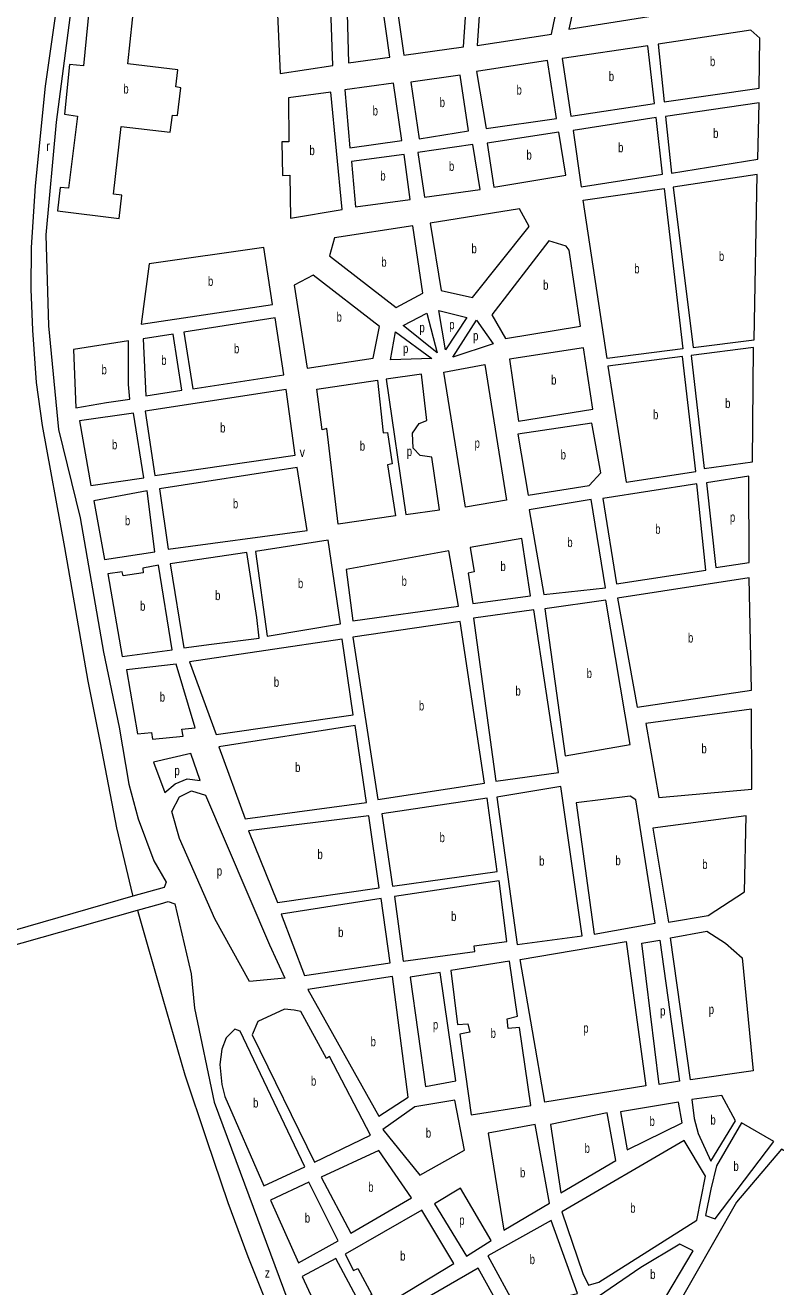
# Model space of a CAD drawing. Extents: x 639657 to 671642, y 222838 to 252123.
# Drawn here: x 649779 to 650568, y 239098 to 240424 of the extents above; entities that cross this region are included whole.
import ezdxf

# ---------------------------------------------------------------- set-up
doc = ezdxf.new("R2010")
doc.units = 0
doc.header["$LTSCALE"] = 4
doc.layers.add('1', color=7, linetype='Continuous', lineweight=13)
doc.layers.add('5', color=7, linetype='Continuous', lineweight=13)
doc.layers.add('7', color=7, linetype='Continuous')

msp = doc.modelspace()

# ---------------------------------------------------------------- linework, layer by layer
at = {"layer": '1'}
msp.add_line((649892.647, 239508.316), (649663.962, 239442.471), dxfattribs=at)
for points in [[(649918.026, 241075.888), (649933.25, 241068.002), (649916.64, 241006.75), (649899.23, 240914.55), (649833.69, 240489.25), (649812, 240322.2), (649801.13, 240203.85), (649803.92, 240108.11), (649814.45, 239999.23), (649837.26, 239906.37), (649861.82, 239765.17), (649878.15, 239686.26), (649888.52, 239626.13), (649898.01, 239589.86), (649914.52, 239545.63), (649927.53, 239523.01), (649925.34, 239517.73), (649892.647, 239508.316)], [(649665.539, 239427.483), (649715.29, 239442.31), (649897.418, 239493.698)], [(649897.418, 239493.698), (649921.63, 239500.53), (649929.68, 239502.7), (649936.8, 239500.43), (649953.91, 239426.9), (649957.52, 239390.57), (649978.06, 239291.74), (650064.64, 239058.86), (650104.11, 238963.89), (650145.17, 238876.98), (650175.39, 238826.04), (650230.01, 238717.98), (650262.92, 238636.13), (650251.614, 238630.278)]]:
    msp.add_lwpolyline(points, dxfattribs=at)
for points in [[(650457.47, 240552.72), (650383.62, 240568.34), (650350.89, 240420.19), (650434.89, 240433.55)], [(650041.99, 240498.37), (650047.42, 240373.59), (650102.77, 240381.72), (650098.7, 240501.47)], [(650147.02, 240502.88), (650116.23, 240501.55), (650119.29, 240384.57), (650162.9, 240390.5)], [(650246.22, 240490.22), (650166.36, 240507.56), (650161.84, 240503.71), (650177.3, 240392.83), (650240.03, 240401.51)], [(650343.68, 240467.24), (650260.17, 240485.89), (650254.42, 240402.98), (650332.84, 240414.85)], [(649816.2, 240253.51), (649813.42, 240229.05), (649878.2, 240221.16), (649881.04, 240245.43), (649872.24, 240246.74), (649880.33, 240317.83), (649931.86, 240311.71), (649934.22, 240329.73), (649939.62, 240329.2), (649942.91, 240358.51), (649937.66, 240359.3), (649939.73, 240377.42), (649887.33, 240383.55), (649894.79, 240453.34), (649905.52, 240451.82), (649907.93, 240476.95), (649842.01, 240483.53), (649838.3, 240458.4), (649847.97, 240457.09), (649840.73, 240381.47), (649826.12, 240382.81), (649820.62, 240330.7), (649834.55, 240328.66), (649824.78, 240252.85)], [(650444.71, 240404.31), (650451.03, 240343.51), (650551.14, 240358.12), (650551.89, 240410.54), (650542.46, 240418.93)], [(650441.15, 240341.81), (650433.97, 240402.4), (650343.95, 240389.27), (650353.06, 240328.46)], [(650337.81, 240326.12), (650328.48, 240386.94), (650253.93, 240375.49), (650263.91, 240315.53)], [(650245.43, 240313.21), (650236.53, 240371.56), (650184.94, 240364.37), (650193.44, 240304.72)], [(650112.53, 240230.56), (650100.76, 240353.89), (650056.07, 240347.97), (650056.62, 240301.57), (650049.11, 240301.58), (650049.89, 240266.35), (650057.59, 240266.53), (650058.18, 240221.44)], [(650175.39, 240302.83), (650166.71, 240363.21), (650115.58, 240356.22), (650120.61, 240295.42)], [(650549.7, 240283.37), (650551.11, 240342.44), (650452.72, 240328.25), (650458.82, 240268.73)], [(650442.62, 240327.2), (650355.39, 240313.63), (650364.08, 240254.11), (650449.37, 240267.46)], [(650340.57, 240311.73), (650264.95, 240300.28), (650272.16, 240253.87), (650347.78, 240266.6)], [(650177.73, 240288.43), (650122.3, 240281.02), (650126.5, 240233.33), (650184.07, 240240.94)], [(650250.13, 240298.81), (650192.34, 240290.33), (650199.33, 240243.27), (650257.76, 240251.53)], [(650481.77, 240085.44), (650545.66, 240093.27), (650548.81, 240267.26), (650460.51, 240253.91)], [(650470.9, 240083.97), (650391.32, 240073.89), (650365.98, 240240.14), (650451.27, 240252.64)], [(650249.58, 240137.91), (650309.23, 240212.55), (650298.96, 240231.04), (650205.28, 240215.98), (650216.74, 240145.28)], [(650169.45, 240127.34), (650197.62, 240142.53), (650186.81, 240213.23), (650104.53, 240200.72), (650099.33, 240181.83)], [(650330.03, 240197.47), (650269.95, 240119.83), (650284.5, 240094.66), (650363.35, 240107.61), (650351.27, 240187.75), (650348.27, 240192.06)], [(650039.52, 240130.39), (650030.41, 240190.35), (649909.67, 240173.41), (649901.17, 240109.84)], [(650145.07, 240074.11), (650151.8, 240107.39), (650082.11, 240161.46), (650062.33, 240150.76), (650075.9, 240063.51)], [(650051.4, 240056.69), (650042.28, 240116.43), (649946.25, 240101.37), (649955.8, 240042.06)], [(650176.6, 240108.55), (650201.536, 240121.458), (650212.503, 240079.908)], [(650214.384, 240124.333), (650243.839, 240116.754), (650221.121, 240083.044)], [(650253.893, 240114.141), (650271.258, 240089.316), (650228.955, 240075.204)], [(650163.595, 240072.448), (650168.633, 240101.859), (650207.019, 240073.636)], [(649864.7, 240027.64), (649889.41, 240031.03), (649888.15, 240046.28), (649888.03, 240092.25), (649830.02, 240083.14), (649832.69, 240021.91)], [(649906.17, 240034.65), (649944.19, 240040.58), (649935.08, 240099.46), (649903.5, 240094.58)], [(650376.06, 240020.58), (650366.53, 240084.83), (650288.54, 240072.96), (650298.07, 240007.85)], [(650411.35, 239943.9), (650484.32, 239954.99), (650470.46, 240075.81), (650392.04, 240065.66)], [(650493.12, 239958.04), (650543.97, 239965.17), (650545.22, 240085.32), (650479.69, 240077.08)], [(650262.603, 240067.603), (650285.359, 239924.685), (650242.272, 239917.63), (650219.554, 240059.525)], [(650096.43, 240000.12), (650091.68, 239998.95), (650086.16, 240041.58), (650149.75, 240050.9), (650155.76, 239995.52), (650160.38, 239995.86), (650165.3, 239963.11), (650160.47, 239962.03), (650168.633, 239908.222), (650108.311, 239899.599)], [(650159.05, 240052.16), (650179.6, 239909.79), (650214.853, 239914.494), (650207.019, 239970.155), (650194.485, 239971.723), (650187.434, 239979.562), (650186.651, 239995.241), (650193.702, 240005.433), (650201.536, 240008.568), (650196.052, 240057.173)], [(650063.22, 239971.97), (650053.69, 240041.35), (649905.49, 240018.29), (649915.57, 239950.63)], [(649904.29, 239948.45), (649893.38, 240016.34), (649836.5, 240008.3), (649848.45, 239940.24)], [(650384.48, 239953.5), (650375.22, 240005.72), (650297.42, 239994.29), (650308.078, 239930.173), (650372.4, 239940.14)], [(650065.4, 239959.08), (649920.44, 239936.67), (649929.74, 239873.32), (650075.79, 239893.05)], [(650485.49, 239941.95), (650386.7, 239926.65), (650400.91, 239836.98), (650494.87, 239851.2)], [(650540.26, 239950.15), (650495.69, 239943.05), (650505.61, 239853.92), (650540.5, 239859.38)], [(649907.55, 239934.49), (649851.72, 239924.13), (649862.63, 239862.39), (649915.78, 239870.59)], [(650324.67, 239825.5), (650389.64, 239832.65), (650374.35, 239925.54), (650309.38, 239914.62)], [(650097.84, 239882.9), (650021.6, 239870.88), (650033.66, 239781.75), (650110.97, 239794.85)], [(650301.41, 239884.52), (650247.16, 239875.19), (650251.55, 239849.47), (650244.95, 239847.94), (650250.03, 239816.17), (650310.71, 239824.39)], [(650012.47, 239869.78), (649931.93, 239857.75), (649946.14, 239769.69), (649975.13, 239773.53), (650025.271, 239779.656), (650022.86, 239801.59)], [(650224.64, 239871.42), (650116.72, 239851.8), (650123.85, 239798.1), (650235, 239813.44)], [(649881.46, 239849.55), (649866.43, 239847.36), (649881.17, 239760.39), (649933.79, 239767.51), (649919.58, 239856.64), (649902.94, 239853.37), (649903.49, 239848.54), (649882.55, 239845.26)], [(650540.55, 239843.27), (650402.03, 239821.95), (650422.69, 239707.02), (650543.02, 239725.1)], [(650313.97, 239809.36), (650250.61, 239800.59), (650274.18, 239629.31), (650340.22, 239638.62)], [(650389.68, 239819.76), (650325.78, 239810.46), (650347.15, 239655.83), (650415.34, 239667.83)], [(650236.65, 239797.33), (650123.9, 239780.91), (650150.15, 239610.18), (650262.37, 239627.13)], [(650112.63, 239778.74), (649952.09, 239754.67), (649980.23, 239678.47), (650124.12, 239699.27)], [(649938.13, 239752.48), (649886.04, 239746.44), (649897.41, 239679.09), (649912.01, 239680.44), (649913.1, 239673.46), (649945.32, 239676.77), (649943.94, 239684.02), (649958.19, 239685.4)], [(650431.93, 239689.89), (650445.57, 239612.05), (650543.3, 239620.9), (650543.07, 239705.23)], [(650126.3, 239688), (649982.95, 239665.59), (650010.55, 239589.93), (650138.34, 239606.92)], [(649914.259, 239649.308), (649926.111, 239617.378), (649937.029, 239626.482), (649949.766, 239631.945), (649963.414, 239630.124), (649953.406, 239658.349)], [(650342.41, 239623.59), (650275.3, 239612.66), (650296.67, 239457.49), (650364.86, 239466.8)], [(650052.299, 239422.071), (650015.274, 239418.895), (649978.881, 239484.449), (649941.578, 239569.123), (649933.39, 239597.347), (649941.578, 239612.825), (649954.315, 239619.198), (649968.873, 239614.646), (650036.2, 239457.135)], [(650265.09, 239611.56), (650154.49, 239595.15), (650165.44, 239518.91), (650275.51, 239534.24)], [(650415.49, 239613.58), (650358.57, 239606.44), (650377.75, 239468.45), (650441.63, 239479.9), (650421.4, 239609.83)], [(650140.53, 239592.96), (650014.2, 239577.04), (650044.63, 239501.93), (650151.48, 239517.26)], [(650537.47, 239592.96), (650439.21, 239579.8), (650455.6, 239481.01), (650497.47, 239488.11), (650535.54, 239512.92)], [(650277.68, 239524.58), (650167.62, 239508.17), (650176.93, 239439.98), (650252.19, 239450.25), (650251.55, 239456.29), (650285.92, 239460.68)], [(650153.66, 239505.98), (650048.42, 239489.59), (650072.97, 239424.95), (650162.97, 239438.33)], [(650457.696, 239464.681), (650496.173, 239471.753), (650515.804, 239459.181), (650533.08, 239443.464), (650544.859, 239324.807), (650478.898, 239315.378)], [(650299.86, 239441.893), (650411.366, 239460.752), (650431.782, 239309.091), (650325.773, 239291.803)], [(650445.739, 239310.383), (650427.856, 239459.181), (650446.702, 239462.324), (650467.119, 239313.806)], [(650288.66, 239440.28), (650226.91, 239430.45), (650234.05, 239373.53), (650244.79, 239374.1), (650246.97, 239365.51), (650236.23, 239363.33), (650248.28, 239278.5), (650311.1, 239288.33), (650299.05, 239370.48), (650287.24, 239369.38), (650286.14, 239379.58), (650296.87, 239382.29)], [(650215.64, 239428.27), (650183.96, 239423.35), (650200.39, 239308.45), (650232.07, 239314.44)], [(650165.45, 239424.04), (650076.58, 239410.26), (650151.06, 239277.16), (650182.16, 239297.12)], [(650024.02, 239376.73), (650018.15, 239362.74), (650083.51, 239228.64), (650142.52, 239257.26), (650099.32, 239339.87), (650096.11, 239337.71), (650069.11, 239387.05), (650062.13, 239388.64), (650051.92, 239389.69)], [(649989.32, 239297.67), (650030.4, 239203.79), (650073.32, 239223.78), (650005.25, 239366.47), (649999.87, 239368.6), (649990.77, 239359.45), (649985.97, 239347.62), (649983.86, 239331.5), (649986.07, 239310.56)], [(650189.17, 239286.93), (650155.39, 239263.21), (650194.2, 239214.97), (650241.39, 239241.42), (650231.05, 239294.03)], [(650466.32, 239291.97), (650405.11, 239281.6), (650412.2, 239241.87), (650470.14, 239269.96)], [(650480.427, 239294.507), (650482.824, 239274.518), (650486.75, 239258.801), (650500.099, 239229.726), (650526.013, 239272.16), (650511.878, 239298.878)], [(650391.15, 239280.49), (650331.56, 239268.51), (650342.5, 239196.57), (650400.42, 239230.56)], [(650315.45, 239268.47), (650266.05, 239259.21), (650282.45, 239157.2), (650330.71, 239185.8)], [(650566.34, 239250.35), (650532.45, 239270.13), (650506.25, 239224.94), (650500.18, 239200.48), (650494.67, 239172.84), (650504.79, 239169.07)], [(650472.34, 239251.7), (650343.63, 239176.7), (650365.64, 239111.8), (650371.77, 239099.43), (650382.5, 239102.68), (650485.46, 239167.95), (650494.46, 239214.16)], [(650151.16, 239241.17), (650090.54, 239213.08), (650121.85, 239154.08), (650185.67, 239191.31)], [(650729.9, 239152.49), (650574.42, 239242.31), (650527.3, 239186.86), (650458.88, 239066.9), (650621.89, 238971.19)], [(650077.66, 239207.67), (650037.43, 239188.77), (650066.61, 239122.78), (650108.45, 239145.99)], [(650209.556, 239184.935), (650243.321, 239129.929), (650269.235, 239146.431), (650237.039, 239201.437)], [(650143.93, 239089.51), (650139.76, 239086.99), (650147.46, 239072.03), (650229.9, 239122.14), (650196.45, 239178.45), (650115.65, 239131.99), (650124.64, 239114.88), (650129, 239116.94)], [(650332.37, 239167.54), (650265.87, 239130.3), (650295.56, 239075.59), (650359.98, 239090.8)], [(650405.77, 239069.07), (650446.15, 239075.89), (650481.78, 239135.71), (650467.8, 239142.65), (650426.75, 239117.9), (650382.01, 239087.64)], [(650070.566, 239108.712), (650099.62, 239045.847), (650138.098, 239067.064), (650105.902, 239127.571)], [(650255.7, 239117.38), (650161.85, 239062.88), (650182.91, 239021.04), (650278.91, 239075.54)]]:
    msp.add_lwpolyline(points, close=True, dxfattribs=at)
at = {"layer": '5'}
for p, q in [((649831.46, 240578.71), (649800.52, 240360.09)), ((649800.52, 240360.09), (649790, 240255.28)), ((649790, 240255.28), (649785.57, 240190.42)), ((649785.57, 240190.42), (649785.48, 240146.81)), ((649785.48, 240146.81), (649786.9, 240103.63)), ((649786.9, 240103.63), (649790.86, 240048.42)), ((649790.86, 240048.42), (649797.35, 240003.5)), ((649797.35, 240003.5), (649820.7, 239875.17)), ((649820.7, 239875.17), (649845.25, 239734.51)), ((649845.25, 239734.51), (649858.32, 239669.55)), ((649858.32, 239669.55), (649875.22, 239580.44)), ((649924.05, 239400.63), (649947.37, 239320.66)), ((649947.37, 239320.66), (649970.11, 239252.5)), ((649970.11, 239252.5), (649992.31, 239186.5)), ((649992.31, 239186.5), (650013.42, 239129.62)), ((650013.42, 239129.62), (650042.62, 239056.65))]:
    msp.add_line(p, q, dxfattribs=at)
for points in [[(649875.22, 239580.44), (649892.358, 239509.51), (649892.647, 239508.316)], [(649897.418, 239493.698), (649897.766, 239492.48), (649924.05, 239400.63)]]:
    msp.add_lwpolyline(points, dxfattribs=at)

# ---------------------------------------------------------------- texts
at = {"layer": '7'}
for s, width, p in [('b', 0.75, (650499.29, 240381.22)), ('b', 0.75, (650392.936, 240365.43)), ('b', 0.75, (649882.561, 240352.345)), ('b', 0.75, (650295.962, 240351.235)), ('b', 0.75, (650144.694, 240329.315)), ('b', 0.75, (650215.153, 240338.14)), ('b', 0.75, (650502.637, 240305.585)), ('r', 0.85, (649801.466, 240292.102)), ('b', 0.75, (650402.747, 240290.655)), ('b', 0.75, (650078.249, 240287.665)), ('b', 0.75, (650306.429, 240282.8)), ('b', 0.75, (650224.908, 240271.04)), ('b', 0.75, (650152.741, 240260.88)), ('b', 0.75, (650248.59, 240184.475)), ('b', 0.75, (650153.781, 240170.285)), ('b', 0.75, (650508.731, 240176.35)), ('b', 0.75, (650419.684, 240163.265)), ('b', 0.75, (649971.539, 240150.095)), ('b', 0.75, (650323.902, 240146.065)), ('b', 0.75, (650106.758, 240112.485)), ('p', 0.75, (650193.858, 240101.381)), ('p', 0.75, (650225.194, 240104.516)), ('p', 0.75, (650250.263, 240092.757)), ('b', 0.75, (649998.885, 240079.245)), ('b', 0.75, (649922.41, 240067.055)), ('p', 0.75, (650176.624, 240079.43)), ('b', 0.75, (649859.639, 240057.08)), ('b', 0.75, (650332.338, 240046.34)), ('b', 0.75, (650515.249, 240021.68)), ('b', 0.75, (650439.458, 240009.855)), ('b', 0.75, (649984.366, 239995.99)), ('b', 0.75, (649870.632, 239978.29)), ('b', 0.75, (650131.15, 239976.85)), ('p', 0.75, (650251.83, 239979.868)), ('v', 0.85, (650067.886, 239970.37)), ('p', 0.75, (650180.541, 239971.245)), ('b', 0.75, (650342.367, 239967.69)), ('b', 0.75, (649997.796, 239916.2)), ('b', 0.75, (649884.226, 239898.44)), ('p', 0.75, (650520.321, 239902.035)), ('b', 0.75, (650441.754, 239889.465)), ('b', 0.75, (650349.336, 239875.52)), ('b', 0.75, (650279.048, 239850.345)), ('b', 0.75, (650066.099, 239832.325)), ('b', 0.75, (650175.086, 239834.76)), ('b', 0.75, (649979.08, 239819.735)), ('b', 0.75, (649900.133, 239808.515)), ('b', 0.75, (650476.209, 239775.145)), ('b', 0.75, (650369.673, 239737.795)), ('b', 0.75, (650040.797, 239728.605)), ('b', 0.75, (650294.801, 239719.335)), ('b', 0.75, (649920.818, 239712.97)), ('b', 0.75, (650193.277, 239703.755)), ('b', 0.75, (650490.302, 239658.64)), ('p', 0.75, (649936.285, 239635.58)), ('b', 0.75, (650063.122, 239638.965)), ('b', 0.75, (650215.06, 239565.235)), ('b', 0.75, (650086.652, 239547.445)), ('b', 0.75, (650319.767, 239540.54)), ('b', 0.75, (650399.889, 239541.015)), ('b', 0.75, (650491.217, 239536.985)), ('p', 0.75, (649980.867, 239529.966)), ('b', 0.75, (650227.145, 239482.28)), ('b', 0.75, (650108.409, 239465.465)), ('p', 0.75, (650446.951, 239382.925)), ('p', 0.75, (650497.992, 239384.497)), ('p', 0.75, (650208.055, 239368.36)), ('p', 0.75, (650366.07, 239364.852)), ('b', 0.75, (650142.542, 239350.6)), ('b', 0.75, (650268.733, 239359.39)), ('b', 0.75, (650079.82, 239309.165)), ('b', 0.75, (650018.943, 239286.195)), ('b', 0.75, (650499.831, 239268.293)), ('b', 0.75, (650200.608, 239254.5)), ('b', 0.75, (650435.8, 239266.92)), ('b', 0.75, (650367.53, 239238.53)), ('b', 0.75, (650523.99, 239219.6)), ('b', 0.75, (650299.613, 239212.835)), ('b', 0.75, (650140.02, 239197.625)), ('b', 0.75, (650415.479, 239175.565)), ('b', 0.75, (650073.345, 239165.225)), ('p', 0.75, (650235.718, 239162.899)), ('b', 0.75, (650173.628, 239125.24)), ('b', 0.75, (650309.761, 239121.565)), ('z', 0.8, (650031.397, 239107.351)), ('b', 0.75, (650436.475, 239105.86))]:
    msp.add_text(s, height=10, dxfattribs=dict(at, width=width)).set_placement(p)

doc.saveas('drawing.dxf')
